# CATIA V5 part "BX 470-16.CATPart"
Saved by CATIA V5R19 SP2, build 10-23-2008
Part number: BX 470-16
Bounding box of the stored display mesh (mm): x -37.351 to 37.491, y -37.46 to 37.351, z 0 to 106
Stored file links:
  C:\Users\Bora\Desktop\3D Katı model\BX serisi\BX 470\BX 470-16.CATPart
  C:\Program Files\Dassault Systemes\B19\intel_a\reffiles\standard\MetricThickPitch.txt
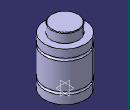
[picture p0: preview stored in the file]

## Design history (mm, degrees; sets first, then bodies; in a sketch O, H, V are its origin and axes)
Body1 (main body)
  Sketch1 on yz-plane, origin (0, 0, 0), H (0, 1, 0), V (0, 0, 1)
    point P1 (37.5, 74.5)
    point P2 (37.5, 69.5)
    point P3 (37.5, 20.5)
    point P4 (37.5, 15.5)
    point P6 (37.5, 74.5)
    point P7 (25, 105)
    point P9 (25, 105)
    point P11 (37.5, 69.5)
    point P12 (37.5, 20.5)
    point P13 (37.5, 15.5)
    arc A1 centre (37.5, 72) radius 2.5 from (37.5, 74.5) to (37.5, 69.5) ccw
    arc A2 centre (37.5, 18) radius 2.5 from (37.5, 20.5) to (37.5, 15.5) ccw
    line L1 (37.5, 89) -> (37.5, 74.5)
    line L2 (25, 105) -> (25, 89)
    arc A3 centre (24, 105) radius 1 from (25, 105) to (24, 106) ccw
    line L3 (37.5, 69.5) -> (37.5, 20.5)
    line L4 (37.5, 15.5) -> (37.5, 0)
    line L5 (24, 106) -> (0, 106)
    line L6 (25, 89) -> (37.5, 89)
    line L7 (37.5, 0) -> (0, 0)
    tangency: L5 A3
    horizontal: L6 H, L7 H
    coincidence: P1 P6, P2 P11, P3 P12, P4 P13, P7 P9
  Shaft1: profile Sketch1, axis Sketch1.V, angle 360
  Sketch2 on face of Shaft1 from Sketch1.L7, origin (0, 0, 0), H (1, 0, 0), V (0, -1, 0)
    point P1 (20, 0)
    distance P1 V = 20
  Hole1: placed by Sketch2, at (20, 0, 0) direction (0, 0, 1), diameter 8, depth 7
  CircPattern1: of the body so far, instances 4, angular step 90, axis from xy-plane
  Sketch3 on face of CircPattern1, origin (0, 0, 0), H (1, 0, 0), V (0, -1, 0)
    point P1 (20, 0)
    distance P1 V = 20
  Hole2: placed by Sketch3, at (20, 0, 0) direction (0, 0, 1), diameter 8, depth 7
  CircPattern2: of the body so far, instances 4, angular step 90, axis from face of CircPattern1
  Sketch4 on face of CircPattern2, origin (0, 0, 0), H (1, 0, 0), V (0, -1, 0)
    point P1 (20, 0)
    distance P1 V = 20
  Hole3: placed by Sketch4, at (20, 0, 0) direction (0, 0, 1), diameter 6.647, depth 7, threaded "M8", thread diameter 8, thread depth 7, pitch 1.25
  CircPattern3: of Hole3, instances 4, angular step 90, axis from xy-plane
